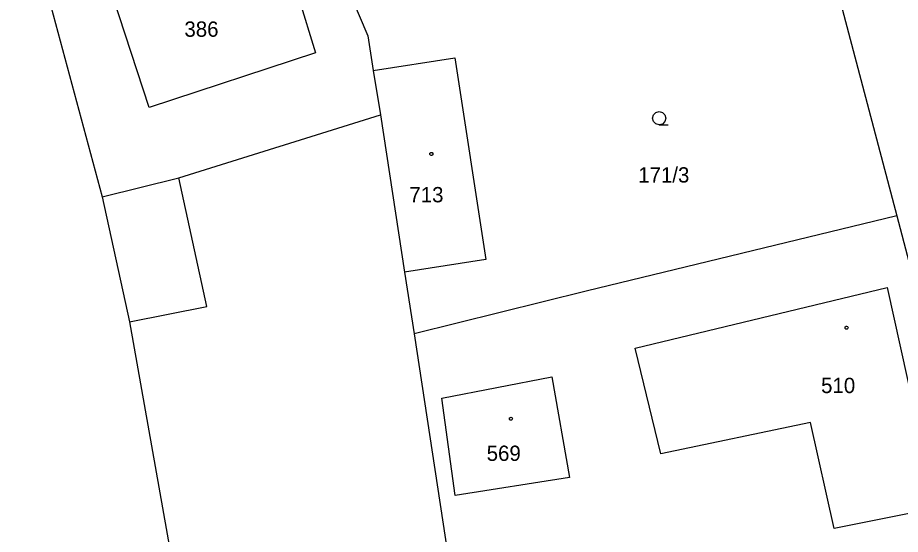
# Model space of a CAD drawing. Extents: x -757994 to -755874, y -1047691 to -1046119.
# Drawn here: x -756488.32 to -756439.22, y -1046660.44 to -1046631.73 of the extents above; entities that cross this region are included whole.
import ezdxf

# ---------------------------------------------------------------- set-up
doc = ezdxf.new("R2010")
doc.units = 0
doc.layers.add('katastrální mapa', color=7, linetype='Continuous')

msp = doc.modelspace()

# ---------------------------------------------------------------- linework, layer by layer
at = {"layer": 'katastrální mapa'}
for p, q in [((-756447.76, -1046611.14), (-756439.42, -1046642.75)), ((-756474.45, -1046619.66), (-756468.84, -1046632.74)), ((-756488.32, -1046624.28), (-756483.62, -1046641.68)), ((-756474.05, -1046626.21), (-756471.75, -1046633.69)), ((-756481, -1046636.72), (-756483.96, -1046627.72)), ((-756468.84, -1046632.74), (-756468.54, -1046634.66)), ((-756471.75, -1046633.69), (-756481, -1046636.72)), ((-756468.54, -1046634.66), (-756464.01, -1046633.96)), ((-756464.01, -1046633.96), (-756462.27, -1046645.17)), ((-756468.54, -1046634.66), (-756468.13, -1046637.13)), ((-756479.35, -1046640.63), (-756468.13, -1046637.13)), ((-756468.13, -1046637.13), (-756466.8, -1046645.88)), ((-756483.62, -1046641.68), (-756479.35, -1046640.63)), ((-756477.8, -1046647.77), (-756479.35, -1046640.63)), ((-756483.62, -1046641.68), (-756482.1, -1046648.63)), ((-756439.42, -1046642.75), (-756456.7, -1046646.92)), ((-756439.42, -1046642.75), (-756432.36, -1046669.71)), ((-756462.27, -1046645.17), (-756466.8, -1046645.88)), ((-756466.8, -1046645.88), (-756466.27, -1046649.3)), ((-756456.7, -1046646.92), (-756466.27, -1046649.3)), ((-756453.98, -1046650.09), (-756439.95, -1046646.72)), ((-756439.95, -1046646.72), (-756437.26, -1046658.98)), ((-756482.1, -1046648.63), (-756477.8, -1046647.77)), ((-756482.1, -1046648.63), (-756476.62, -1046679.34)), ((-756466.27, -1046649.3), (-756461.31, -1046681.72)), ((-756452.54, -1046655.96), (-756453.98, -1046650.09)), ((-756464.73, -1046652.87), (-756458.6, -1046651.68)), ((-756458.6, -1046651.68), (-756457.63, -1046657.28)), ((-756463.98, -1046658.29), (-756464.73, -1046652.87)), ((-756444.22, -1046654.22), (-756452.54, -1046655.96)), ((-756442.9, -1046660.12), (-756444.22, -1046654.22)), ((-756457.63, -1046657.28), (-756463.98, -1046658.29)), ((-756437.26, -1046658.98), (-756442.9, -1046660.12))]:
    msp.add_line(p, q, dxfattribs=at)
msp.add_lwpolyline([(-756452.63, -1046637.68), (-756452.82, -1046637.63), (-756452.955, -1046637.495), (-756453.005, -1046637.31), (-756452.955, -1046637.125), (-756452.82, -1046636.99), (-756452.635, -1046636.94), (-756452.45, -1046636.99), (-756452.315, -1046637.125), (-756452.265, -1046637.315), (-756452.315, -1046637.505), (-756452.45, -1046637.64), (-756452.64, -1046637.69), (-756452.14, -1046637.69)], dxfattribs=at)
for points in [[(-756465.31, -1046639.215), (-756465.26, -1046639.225), (-756465.235, -1046639.27), (-756465.225, -1046639.3), (-756465.235, -1046639.345), (-756465.275, -1046639.38), (-756465.31, -1046639.385), (-756465.355, -1046639.37), (-756465.385, -1046639.34), (-756465.395, -1046639.3), (-756465.385, -1046639.255), (-756465.345, -1046639.22)], [(-756442.21, -1046648.875), (-756442.16, -1046648.885), (-756442.135, -1046648.93), (-756442.125, -1046648.96), (-756442.135, -1046649.005), (-756442.175, -1046649.04), (-756442.21, -1046649.045), (-756442.255, -1046649.03), (-756442.285, -1046649), (-756442.295, -1046648.96), (-756442.285, -1046648.915), (-756442.245, -1046648.88)], [(-756460.88, -1046653.935), (-756460.83, -1046653.945), (-756460.805, -1046653.99), (-756460.795, -1046654.02), (-756460.805, -1046654.065), (-756460.845, -1046654.1), (-756460.88, -1046654.105), (-756460.925, -1046654.09), (-756460.955, -1046654.06), (-756460.965, -1046654.02), (-756460.955, -1046653.975), (-756460.915, -1046653.94)]]:
    msp.add_lwpolyline(points, close=True, dxfattribs=at)

# ---------------------------------------------------------------- texts
for s, p in [('386', (-756479.044, -1046632.79)), ('171/3', (-756453.802, -1046640.89)), ('713', (-756466.531, -1046641.99)), ('510', (-756443.63, -1046652.59)), ('569', (-756462.231, -1046656.36))]:
    msp.add_text(s, height=0.85, dxfattribs=at).set_placement(p)

doc.saveas('drawing.dxf')
